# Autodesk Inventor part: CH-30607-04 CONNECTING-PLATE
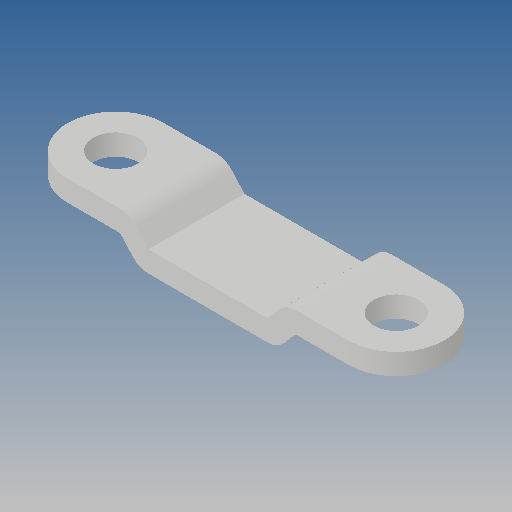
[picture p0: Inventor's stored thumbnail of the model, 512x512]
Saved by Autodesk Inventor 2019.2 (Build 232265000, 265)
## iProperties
Created: 2012-09
Part Number: CH-30607-04 CONNECTING-PLATE
Material: Ogólny
Document SubType Name: Modeling
Designer: CADENGINEERING4
Density: 1 g/cm^3
Appearance: Domyślna
Author: CADENGINEERING4
Revision Number: ÈÎºÎ
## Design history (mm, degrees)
feature "ÇÐ³ý-À­Éì1"
node "Bryła1"
